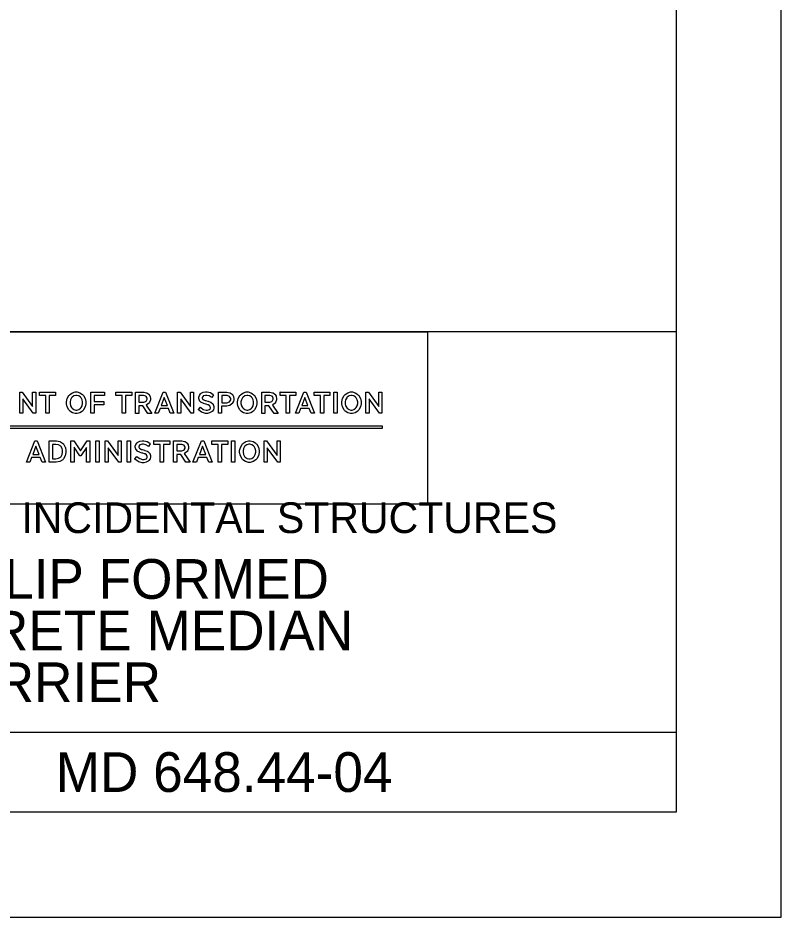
# Model space of a CAD drawing. Extents: x -111.7 to -103.2, y -200 to -189.
# Drawn here: x -105.536 to -103.232, y -199.986 to -197.271 of the extents above; entities that cross this region are included whole.
import ezdxf

# ---------------------------------------------------------------- set-up
doc = ezdxf.new("R2010")
doc.units = 0
for name, color, linetype in [('BORD-LINE', 7, 'Continuous'), ('Level 13', 7, 'Continuous'), ('MSHA-LOGO', 7, 'Continuous'), ('TTLB-TEXT', 7, 'Continuous'), ('USER-CLIP', 7, 'Continuous'), ('USER-LINE', 7, 'Continuous')]:
    doc.layers.add(name, color=color, linetype=linetype)

msp = doc.modelspace()

# ---------------------------------------------------------------- linework, layer by layer
at = {"layer": 'BORD-LINE'}
for p, q in [((-103.5488, -198.2184), (-108.0217, -198.2184)), ((-108.0217, -199.4274), (-103.5488, -199.4274))]:
    msp.add_line(p, q, dxfattribs=at)
msp.add_lwpolyline([(-110.923, -189.3161), (-103.5488, -189.3161), (-103.5488, -199.6692), (-110.923, -199.6692)], close=True, dxfattribs=at)
at = {"layer": 'MSHA-LOGO'}
for points in [[(-105.4898, -198.4647), (-105.5212, -198.4212), (-105.5212, -198.4647), (-105.5307, -198.4647), (-105.5307, -198.4012), (-105.5231, -198.4012), (-105.4917, -198.4446), (-105.4917, -198.4012), (-105.4822, -198.4012), (-105.4822, -198.4647)], [(-105.4708, -198.4008), (-105.4227, -198.4008), (-105.4227, -198.411), (-105.4417, -198.411), (-105.4417, -198.4643), (-105.4515, -198.4643), (-105.4515, -198.411), (-105.4705, -198.411), (-105.4705, -198.4008)], [(-105.3805, -198.4097), (-105.3791, -198.4081), (-105.3712, -198.4026), (-105.3627, -198.4002), (-105.3599, -198.4002), (-105.3571, -198.4002), (-105.3486, -198.4024), (-105.3406, -198.4078), (-105.3392, -198.4094), (-105.3379, -198.4109), (-105.3329, -198.4198), (-105.3307, -198.4295), (-105.3307, -198.4327), (-105.3307, -198.4359), (-105.3329, -198.4455), (-105.3379, -198.4545), (-105.3392, -198.4561), (-105.3406, -198.4577), (-105.3486, -198.463), (-105.3571, -198.4653), (-105.3599, -198.4653), (-105.3627, -198.4653), (-105.3712, -198.463), (-105.3791, -198.4577), (-105.3805, -198.4561), (-105.3819, -198.4545), (-105.3868, -198.4456), (-105.389, -198.4359), (-105.389, -198.4327), (-105.389, -198.4296), (-105.3868, -198.4201), (-105.3819, -198.4113)], [(-105.373, -198.4485), (-105.3721, -198.4496), (-105.3669, -198.4533), (-105.3614, -198.4548), (-105.3595, -198.4548), (-105.3577, -198.4548), (-105.3522, -198.4533), (-105.347, -198.4496), (-105.3461, -198.4485), (-105.3452, -198.4475), (-105.342, -198.4416), (-105.3406, -198.4349), (-105.3406, -198.4327), (-105.3406, -198.4305), (-105.342, -198.4238), (-105.3452, -198.4179), (-105.3461, -198.4169), (-105.347, -198.4159), (-105.3522, -198.4122), (-105.3577, -198.4107), (-105.3595, -198.4107), (-105.3614, -198.4107), (-105.3669, -198.4122), (-105.3721, -198.4159), (-105.373, -198.4169), (-105.3739, -198.4179), (-105.3771, -198.4238), (-105.3785, -198.4305), (-105.3785, -198.4327), (-105.3785, -198.4349), (-105.3772, -198.4416), (-105.374, -198.4475)], [(-105.316, -198.4008), (-105.2741, -198.4008), (-105.2741, -198.411), (-105.3062, -198.411), (-105.3062, -198.4291), (-105.2764, -198.4291), (-105.2764, -198.4393), (-105.3062, -198.4393), (-105.3062, -198.4643), (-105.316, -198.4643)], [(-105.2404, -198.4008), (-105.1923, -198.4008), (-105.1923, -198.411), (-105.2113, -198.411), (-105.2113, -198.4643), (-105.2211, -198.4643), (-105.2211, -198.411), (-105.2401, -198.411), (-105.2401, -198.4008)], [(-105.1809, -198.4646), (-105.1809, -198.4012), (-105.1586, -198.4012), (-105.1558, -198.4012), (-105.1483, -198.4025), (-105.1475, -198.4028), (-105.1468, -198.403), (-105.141, -198.4069), (-105.1406, -198.4074), (-105.1402, -198.4079), (-105.1373, -198.4131), (-105.137, -198.4137), (-105.1368, -198.4142), (-105.136, -198.4195), (-105.136, -198.4212), (-105.136, -198.4241), (-105.1387, -198.4319), (-105.1393, -198.4327), (-105.1399, -198.4336), (-105.1475, -198.4393), (-105.1485, -198.4397), (-105.1314, -198.465), (-105.1435, -198.465), (-105.1589, -198.4416), (-105.171, -198.4416), (-105.171, -198.465), (-105.1809, -198.465)], [(-105.171, -198.4113), (-105.171, -198.4308), (-105.1583, -198.4308), (-105.1561, -198.4308), (-105.15, -198.4285), (-105.1494, -198.4281), (-105.149, -198.4277), (-105.1462, -198.4223), (-105.1462, -198.4206), (-105.1462, -198.4188), (-105.1486, -198.4141), (-105.1491, -198.4137), (-105.1496, -198.4132), (-105.1564, -198.4113), (-105.1586, -198.4113)], [(-105.0977, -198.4008), (-105.0902, -198.4008), (-105.0653, -198.4643), (-105.0758, -198.4643), (-105.0814, -198.4502), (-105.1069, -198.4502), (-105.1125, -198.4643), (-105.1226, -198.4643)], [(-105.1033, -198.441), (-105.0846, -198.441), (-105.0941, -198.4169)], [(-105.013, -198.4646), (-105.0444, -198.4212), (-105.0444, -198.4646), (-105.0539, -198.4646), (-105.0539, -198.4012), (-105.0464, -198.4012), (-105.0149, -198.4446), (-105.0149, -198.4012), (-105.0055, -198.4012), (-105.0055, -198.4646)], [(-104.9567, -198.4423), (-104.957, -198.4419), (-104.9611, -198.4392), (-104.9616, -198.439), (-104.9621, -198.4388), (-104.9678, -198.4372), (-104.9685, -198.437), (-104.9691, -198.4368), (-104.9754, -198.435), (-104.976, -198.4347), (-104.9767, -198.4345), (-104.9824, -198.4318), (-104.9829, -198.4314), (-104.9834, -198.4311), (-104.9875, -198.4267), (-104.9878, -198.4261), (-104.9881, -198.4256), (-104.9897, -198.4198), (-104.9897, -198.4179), (-104.9897, -198.4162), (-104.9882, -198.411), (-104.9846, -198.406), (-104.9835, -198.4051), (-104.9825, -198.4042), (-104.9764, -198.4011), (-104.9697, -198.3998), (-104.9675, -198.3998), (-104.9644, -198.3998), (-104.955, -198.4021), (-104.9469, -198.4075), (-104.9456, -198.409), (-104.9508, -198.4169), (-104.952, -198.4159), (-104.9587, -198.412), (-104.9655, -198.4104), (-104.9678, -198.4104), (-104.9699, -198.4104), (-104.9758, -198.412), (-104.9763, -198.4123), (-104.9769, -198.4127), (-104.9796, -198.4166), (-104.9796, -198.4179), (-104.9796, -198.4192), (-104.9774, -198.4225), (-104.977, -198.4229), (-104.9766, -198.4232), (-104.9711, -198.4257), (-104.9704, -198.4258), (-104.9698, -198.426), (-104.9627, -198.4279), (-104.9619, -198.4281), (-104.9612, -198.4284), (-104.9541, -198.4311), (-104.9534, -198.4314), (-104.9528, -198.4318), (-104.9473, -198.4363), (-104.9469, -198.437), (-104.9465, -198.4377), (-104.9443, -198.4441), (-104.9443, -198.4462), (-104.9443, -198.4481), (-104.9458, -198.4537), (-104.9494, -198.4588), (-104.9505, -198.4597), (-104.9515, -198.4606), (-104.9576, -198.4637), (-104.9638, -198.465), (-104.9659, -198.465), (-104.9695, -198.465), (-104.9791, -198.4622), (-104.9803, -198.4617), (-104.9814, -198.4611), (-104.9904, -198.4543), (-104.991, -198.4535), (-104.9852, -198.4459), (-104.9839, -198.4474), (-104.9763, -198.4527), (-104.968, -198.4551), (-104.9652, -198.4551), (-104.9632, -198.4551), (-104.9578, -198.4535), (-104.9574, -198.4531), (-104.9569, -198.4528), (-104.9544, -198.4488), (-104.9544, -198.4475), (-104.9545, -198.4469), (-104.9564, -198.4426)], [(-104.9305, -198.4646), (-104.9305, -198.4012), (-104.9076, -198.4012), (-104.9047, -198.4012), (-104.8966, -198.4025), (-104.8958, -198.4028), (-104.895, -198.4031), (-104.889, -198.4072), (-104.8886, -198.4077), (-104.8882, -198.4082), (-104.8852, -198.4137), (-104.885, -198.4143), (-104.8849, -198.4149), (-104.884, -198.4201), (-104.884, -198.4219), (-104.884, -198.4238), (-104.8851, -198.4289), (-104.8854, -198.4294), (-104.8856, -198.43), (-104.8889, -198.4355), (-104.8893, -198.436), (-104.8897, -198.4365), (-104.896, -198.4406), (-104.8968, -198.441), (-104.8976, -198.4413), (-104.9054, -198.4426), (-104.9079, -198.4426), (-104.921, -198.4426), (-104.921, -198.4643), (-104.9305, -198.4643)], [(-104.9204, -198.4113), (-104.9204, -198.4327), (-104.9073, -198.4327), (-104.9047, -198.4327), (-104.897, -198.43), (-104.8935, -198.4239), (-104.8935, -198.4219), (-104.8935, -198.4199), (-104.8968, -198.414), (-104.9042, -198.4113), (-104.9066, -198.4113)], [(-104.8644, -198.4097), (-104.863, -198.4081), (-104.8551, -198.4026), (-104.8466, -198.4002), (-104.8438, -198.4002), (-104.841, -198.4002), (-104.8325, -198.4024), (-104.8246, -198.4078), (-104.8232, -198.4094), (-104.8218, -198.4109), (-104.8168, -198.4198), (-104.8147, -198.4295), (-104.8147, -198.4327), (-104.8147, -198.4359), (-104.8168, -198.4455), (-104.8218, -198.4545), (-104.8232, -198.4561), (-104.8246, -198.4577), (-104.8325, -198.463), (-104.841, -198.4653), (-104.8438, -198.4653), (-104.8466, -198.4653), (-104.8551, -198.463), (-104.863, -198.4577), (-104.8644, -198.4561), (-104.8658, -198.4545), (-104.8708, -198.4456), (-104.8729, -198.4359), (-104.8729, -198.4327), (-104.8728, -198.4304), (-104.8706, -198.4201), (-104.8658, -198.4113)], [(-104.8569, -198.4485), (-104.856, -198.4496), (-104.8508, -198.4533), (-104.8453, -198.4548), (-104.8435, -198.4548), (-104.8416, -198.4548), (-104.8361, -198.4533), (-104.831, -198.4496), (-104.8301, -198.4485), (-104.8292, -198.4475), (-104.8259, -198.4416), (-104.8245, -198.4349), (-104.8245, -198.4327), (-104.8245, -198.4305), (-104.8259, -198.4238), (-104.8292, -198.4179), (-104.8301, -198.4169), (-104.831, -198.4159), (-104.8361, -198.4122), (-104.8416, -198.4107), (-104.8435, -198.4107), (-104.8453, -198.4107), (-104.8507, -198.4122), (-104.8559, -198.4159), (-104.8569, -198.4169), (-104.8578, -198.4179), (-104.861, -198.4238), (-104.8625, -198.4305), (-104.8625, -198.4327), (-104.8625, -198.4349), (-104.8612, -198.4416), (-104.8579, -198.4475)], [(-104.7999, -198.4646), (-104.7999, -198.4012), (-104.7777, -198.4012), (-104.7749, -198.4012), (-104.7674, -198.4025), (-104.7666, -198.4028), (-104.7658, -198.403), (-104.7601, -198.4069), (-104.7597, -198.4074), (-104.7593, -198.4079), (-104.7563, -198.4131), (-104.7561, -198.4137), (-104.7559, -198.4142), (-104.7551, -198.4195), (-104.7551, -198.4212), (-104.7551, -198.4241), (-104.7578, -198.4319), (-104.7584, -198.4327), (-104.759, -198.4336), (-104.7666, -198.4393), (-104.7675, -198.4397), (-104.7505, -198.465), (-104.7626, -198.465), (-104.778, -198.4416), (-104.7901, -198.4416), (-104.7901, -198.465), (-104.7999, -198.465)], [(-104.7901, -198.4113), (-104.7901, -198.4308), (-104.7774, -198.4308), (-104.7752, -198.4308), (-104.7691, -198.4285), (-104.7685, -198.4281), (-104.768, -198.4277), (-104.7652, -198.4223), (-104.7652, -198.4206), (-104.7652, -198.4188), (-104.7677, -198.4141), (-104.7682, -198.4137), (-104.7687, -198.4132), (-104.7754, -198.4113), (-104.7777, -198.4113)], [(-104.745, -198.4008), (-104.6968, -198.4008), (-104.6968, -198.411), (-104.7158, -198.411), (-104.7158, -198.4643), (-104.7257, -198.4643), (-104.7257, -198.411), (-104.7446, -198.411), (-104.7446, -198.4008)], [(-104.673, -198.4008), (-104.6654, -198.4008), (-104.6406, -198.4643), (-104.651, -198.4643), (-104.6566, -198.4502), (-104.6825, -198.4502), (-104.688, -198.4643), (-104.6978, -198.4643)], [(-104.6788, -198.441), (-104.6602, -198.441), (-104.6697, -198.4169)], [(-104.6419, -198.4008), (-104.5938, -198.4008), (-104.5938, -198.411), (-104.6128, -198.411), (-104.6128, -198.4643), (-104.6226, -198.4643), (-104.6226, -198.411), (-104.6416, -198.411), (-104.6416, -198.4008)], [(-104.5823, -198.4008), (-104.5725, -198.4008), (-104.5725, -198.4643), (-104.5823, -198.4643)], [(-104.5496, -198.4097), (-104.5482, -198.4081), (-104.5403, -198.4026), (-104.5318, -198.4002), (-104.529, -198.4002), (-104.5262, -198.4002), (-104.5177, -198.4024), (-104.5098, -198.4078), (-104.5084, -198.4094), (-104.507, -198.4109), (-104.502, -198.4198), (-104.4998, -198.4295), (-104.4998, -198.4327), (-104.4998, -198.4359), (-104.502, -198.4455), (-104.507, -198.4545), (-104.5084, -198.4561), (-104.5098, -198.4577), (-104.5177, -198.463), (-104.5262, -198.4653), (-104.529, -198.4653), (-104.5318, -198.4653), (-104.5403, -198.463), (-104.5482, -198.4577), (-104.5496, -198.4561), (-104.551, -198.4545), (-104.5559, -198.4456), (-104.5581, -198.4359), (-104.5581, -198.4327), (-104.5581, -198.4296), (-104.5561, -198.4201), (-104.5511, -198.4113)], [(-104.5424, -198.4485), (-104.5415, -198.4496), (-104.5363, -198.4533), (-104.5308, -198.4548), (-104.529, -198.4548), (-104.5272, -198.4548), (-104.5217, -198.4533), (-104.5165, -198.4496), (-104.5156, -198.4485), (-104.5147, -198.4475), (-104.5114, -198.4416), (-104.51, -198.4349), (-104.51, -198.4327), (-104.51, -198.4305), (-104.5114, -198.4238), (-104.5147, -198.4179), (-104.5156, -198.4169), (-104.5165, -198.4159), (-104.5217, -198.4122), (-104.5272, -198.4107), (-104.529, -198.4107), (-104.5308, -198.4107), (-104.5362, -198.4122), (-104.5414, -198.4159), (-104.5424, -198.4169), (-104.5433, -198.4179), (-104.5465, -198.4238), (-104.5479, -198.4305), (-104.5479, -198.4327), (-104.5479, -198.4349), (-104.5465, -198.4416), (-104.5433, -198.4475)], [(-104.4445, -198.4646), (-104.4759, -198.4212), (-104.4759, -198.4646), (-104.4854, -198.4646), (-104.4854, -198.4012), (-104.4779, -198.4012), (-104.4465, -198.4446), (-104.4465, -198.4012), (-104.437, -198.4012), (-104.437, -198.4646)], [(-106.5526, -198.5026), (-104.4359, -198.5026), (-104.4359, -198.5105), (-106.5526, -198.5105)], [(-105.4854, -198.5481), (-105.4777, -198.5481), (-105.4525, -198.6124), (-105.463, -198.6124), (-105.4684, -198.5982), (-105.4946, -198.5982), (-105.5001, -198.6124), (-105.5103, -198.6124)], [(-105.4413, -198.5481), (-105.4234, -198.5481), (-105.4196, -198.5481), (-105.4094, -198.5503), (-105.4084, -198.5507), (-105.4073, -198.5511), (-105.3988, -198.557), (-105.3981, -198.5578), (-105.3975, -198.5585), (-105.393, -198.5667), (-105.3927, -198.5677), (-105.3924, -198.5687), (-105.3911, -198.5769), (-105.3911, -198.5796), (-105.3911, -198.5829), (-105.3932, -198.5928), (-105.3981, -198.6018), (-105.3994, -198.6034), (-105.4008, -198.6049), (-105.4098, -198.6101), (-105.4207, -198.6124), (-105.4243, -198.6124), (-105.4413, -198.6124)], [(-105.4314, -198.5587), (-105.4314, -198.6021), (-105.4237, -198.6021), (-105.4212, -198.6021), (-105.4138, -198.6006), (-105.4077, -198.597), (-105.4068, -198.596), (-105.4058, -198.5949), (-105.4026, -198.5887), (-105.4013, -198.5819), (-105.4013, -198.5796), (-105.4013, -198.5773), (-105.4027, -198.5705), (-105.4069, -198.564), (-105.4138, -198.56), (-105.421, -198.5587), (-105.4234, -198.5587)], [(-105.3764, -198.5481), (-105.3675, -198.5481), (-105.347, -198.578), (-105.3272, -198.5481), (-105.3186, -198.5481), (-105.3186, -198.6124), (-105.3285, -198.6124), (-105.3285, -198.5677), (-105.3461, -198.5931), (-105.3486, -198.5931), (-105.3665, -198.5674), (-105.3665, -198.612), (-105.3764, -198.612)], [(-105.3007, -198.5481), (-105.2908, -198.5481), (-105.2908, -198.6124), (-105.3007, -198.6124)], [(-105.2317, -198.6124), (-105.2633, -198.5687), (-105.2633, -198.6124), (-105.2729, -198.6124), (-105.2729, -198.5481), (-105.2652, -198.5481), (-105.2336, -198.5921), (-105.2336, -198.5481), (-105.224, -198.5481), (-105.224, -198.6124)], [(-105.2064, -198.5481), (-105.1965, -198.5481), (-105.1965, -198.6124), (-105.2064, -198.6124)], [(-105.1476, -198.5902), (-105.148, -198.5899), (-105.1522, -198.5872), (-105.1528, -198.587), (-105.1533, -198.5868), (-105.1592, -198.5849), (-105.1598, -198.5847), (-105.1604, -198.5846), (-105.1668, -198.5827), (-105.1675, -198.5825), (-105.1681, -198.5822), (-105.1739, -198.5796), (-105.1745, -198.5793), (-105.1751, -198.5789), (-105.1793, -198.5744), (-105.1796, -198.5738), (-105.1799, -198.5733), (-105.1815, -198.5674), (-105.1815, -198.5655), (-105.1815, -198.5637), (-105.1799, -198.5584), (-105.1762, -198.5535), (-105.1751, -198.5526), (-105.1741, -198.5517), (-105.168, -198.5487), (-105.1611, -198.5475), (-105.1588, -198.5475), (-105.1557, -198.5475), (-105.1461, -198.5498), (-105.1378, -198.5553), (-105.1365, -198.5568), (-105.1419, -198.5648), (-105.1431, -198.5637), (-105.1498, -198.5598), (-105.1568, -198.5581), (-105.1591, -198.5581), (-105.1613, -198.5581), (-105.1672, -198.5597), (-105.1678, -198.56), (-105.1683, -198.5603), (-105.1713, -198.5644), (-105.1713, -198.5658), (-105.1713, -198.5671), (-105.1691, -198.5705), (-105.1687, -198.5709), (-105.1683, -198.5712), (-105.1628, -198.5737), (-105.162, -198.5738), (-105.1613, -198.574), (-105.1542, -198.5761), (-105.1534, -198.5764), (-105.1526, -198.5766), (-105.1454, -198.5793), (-105.1448, -198.5796), (-105.1441, -198.5799), (-105.1385, -198.5847), (-105.1381, -198.5854), (-105.1377, -198.586), (-105.1355, -198.5925), (-105.1355, -198.5947), (-105.1355, -198.5966), (-105.1371, -198.6023), (-105.1409, -198.6076), (-105.1419, -198.6085), (-105.1429, -198.6094), (-105.149, -198.6125), (-105.1554, -198.614), (-105.1575, -198.614), (-105.1612, -198.614), (-105.171, -198.6113), (-105.1722, -198.6108), (-105.1734, -198.6102), (-105.1825, -198.6032), (-105.1831, -198.6024), (-105.177, -198.5947), (-105.1758, -198.5962), (-105.1681, -198.6016), (-105.1595, -198.604), (-105.1566, -198.604), (-105.1546, -198.604), (-105.1491, -198.6024), (-105.1486, -198.6021), (-105.1481, -198.6017), (-105.1457, -198.5977), (-105.1457, -198.5963), (-105.1457, -198.5948), (-105.1473, -198.5905)], [(-105.1263, -198.5481), (-105.0777, -198.5481), (-105.0777, -198.5587), (-105.0968, -198.5587), (-105.0968, -198.6124), (-105.1067, -198.6124), (-105.1067, -198.5587), (-105.1259, -198.5587), (-105.1259, -198.5481)], [(-105.0662, -198.6124), (-105.0662, -198.5481), (-105.0435, -198.5481), (-105.0407, -198.5481), (-105.0331, -198.5495), (-105.0323, -198.5497), (-105.0315, -198.55), (-105.0257, -198.5537), (-105.0253, -198.5542), (-105.0249, -198.5547), (-105.0219, -198.5601), (-105.0218, -198.5606), (-105.0216, -198.5612), (-105.0208, -198.5663), (-105.0208, -198.568), (-105.0208, -198.5709), (-105.0238, -198.5788), (-105.0243, -198.5796), (-105.0249, -198.5804), (-105.0326, -198.5861), (-105.0336, -198.5863), (-105.0163, -198.612), (-105.0285, -198.612), (-105.0441, -198.5886), (-105.0563, -198.5886), (-105.0563, -198.612), (-105.0662, -198.612)], [(-105.0563, -198.5587), (-105.0563, -198.5783), (-105.0435, -198.5783), (-105.0413, -198.5783), (-105.0351, -198.5761), (-105.0345, -198.5757), (-105.034, -198.5753), (-105.0313, -198.5701), (-105.0313, -198.5684), (-105.0313, -198.5666), (-105.0338, -198.5617), (-105.0342, -198.5613), (-105.0347, -198.5609), (-105.0415, -198.5587), (-105.0438, -198.5587)], [(-104.9821, -198.5481), (-104.9745, -198.5481), (-104.9492, -198.6124), (-104.9598, -198.6124), (-104.9655, -198.5982), (-104.9917, -198.5982), (-104.9972, -198.6124), (-105.0074, -198.6124)], [(-104.9508, -198.5481), (-104.9023, -198.5481), (-104.9023, -198.5587), (-104.9214, -198.5587), (-104.9214, -198.6124), (-104.9313, -198.6124), (-104.9313, -198.5587), (-104.9505, -198.5587), (-104.9505, -198.5481)], [(-104.8908, -198.5481), (-104.8809, -198.5481), (-104.8809, -198.6124), (-104.8908, -198.6124)], [(-104.8579, -198.5571), (-104.8564, -198.5555), (-104.8483, -198.5499), (-104.8399, -198.5475), (-104.8371, -198.5475), (-104.8343, -198.5475), (-104.8258, -198.5498), (-104.8177, -198.5553), (-104.8163, -198.5568), (-104.815, -198.5583), (-104.81, -198.5673), (-104.8077, -198.577), (-104.8077, -198.5802), (-104.8077, -198.5834), (-104.8099, -198.593), (-104.8149, -198.6021), (-104.8163, -198.6037), (-104.8178, -198.6053), (-104.8259, -198.6107), (-104.8343, -198.613), (-104.8371, -198.613), (-104.84, -198.613), (-104.8486, -198.6106), (-104.8565, -198.6052), (-104.8579, -198.6037), (-104.8593, -198.6021), (-104.8643, -198.5932), (-104.8665, -198.5835), (-104.8665, -198.5802), (-104.8665, -198.5771), (-104.8643, -198.5676), (-104.8593, -198.5586)], [(-104.8505, -198.5963), (-104.8496, -198.5973), (-104.8443, -198.6009), (-104.8389, -198.6024), (-104.8371, -198.6024), (-104.8352, -198.6024), (-104.8296, -198.6009), (-104.8243, -198.5973), (-104.8233, -198.5963), (-104.8224, -198.5952), (-104.8192, -198.5892), (-104.8179, -198.5825), (-104.8179, -198.5802), (-104.8179, -198.578), (-104.8194, -198.5714), (-104.8227, -198.5652), (-104.8237, -198.5642), (-104.8246, -198.5631), (-104.8299, -198.5596), (-104.8353, -198.5581), (-104.8371, -198.5581), (-104.8389, -198.5581), (-104.8444, -198.5596), (-104.8496, -198.5631), (-104.8505, -198.5642), (-104.8514, -198.5652), (-104.8545, -198.5712), (-104.8559, -198.578), (-104.8559, -198.5802), (-104.8559, -198.5825), (-104.8545, -198.5892), (-104.8514, -198.5952)], [(-104.7515, -198.6124), (-104.7831, -198.5687), (-104.7831, -198.6124), (-104.7927, -198.6124), (-104.7927, -198.5481), (-104.785, -198.5481), (-104.7534, -198.5921), (-104.7534, -198.5481), (-104.7438, -198.5481), (-104.7438, -198.6124)], [(-105.4911, -198.5886), (-105.4723, -198.5886), (-105.4819, -198.5642)], [(-104.9879, -198.5886), (-104.969, -198.5886), (-104.9786, -198.5642)]]:
    msp.add_lwpolyline(points, close=True, dxfattribs=at)
at = {"layer": 'USER-CLIP'}
msp.add_lwpolyline([(-103.2319, -188.9861), (-111.7319, -188.9861), (-111.7319, -199.9861), (-103.2319, -199.9861)], close=True, dxfattribs=at)
at = {"layer": 'USER-LINE'}
msp.add_lwpolyline([(-104.2997, -198.7391), (-107.2709, -198.7391), (-107.2709, -198.2184), (-104.2997, -198.2184)], close=True, dxfattribs=at)

# ---------------------------------------------------------------- texts
at = {"layer": 'BORD-LINE'}
msp.add_text('HDVBARREIRA', height=6e-12, rotation=180, dxfattribs=at).set_placement((-103.5488, -198.2184))
at = {"layer": 'Level 13'}
for s, p in [('DIAGONAL BAR FOR SLIP FORMED', (-107.3164, -199.025)), ('DOUBLE FACED CONCRETE MEDIAN', (-107.3857, -199.181)), ('TRAFFIC BARRIER', (-106.539, -199.337)), ('MD 648.44-04', (-105.4218, -199.6083))]:
    msp.add_text(s, height=0.12, dxfattribs=at).set_placement(p)
at = {"layer": 'TTLB-TEXT'}
msp.add_text('STANDARDS FOR HIGHWAYS AND INCIDENTAL STRUCTURES', height=0.09269, dxfattribs=at).set_placement((-107.6259, -198.8264))

doc.saveas('drawing.dxf')
